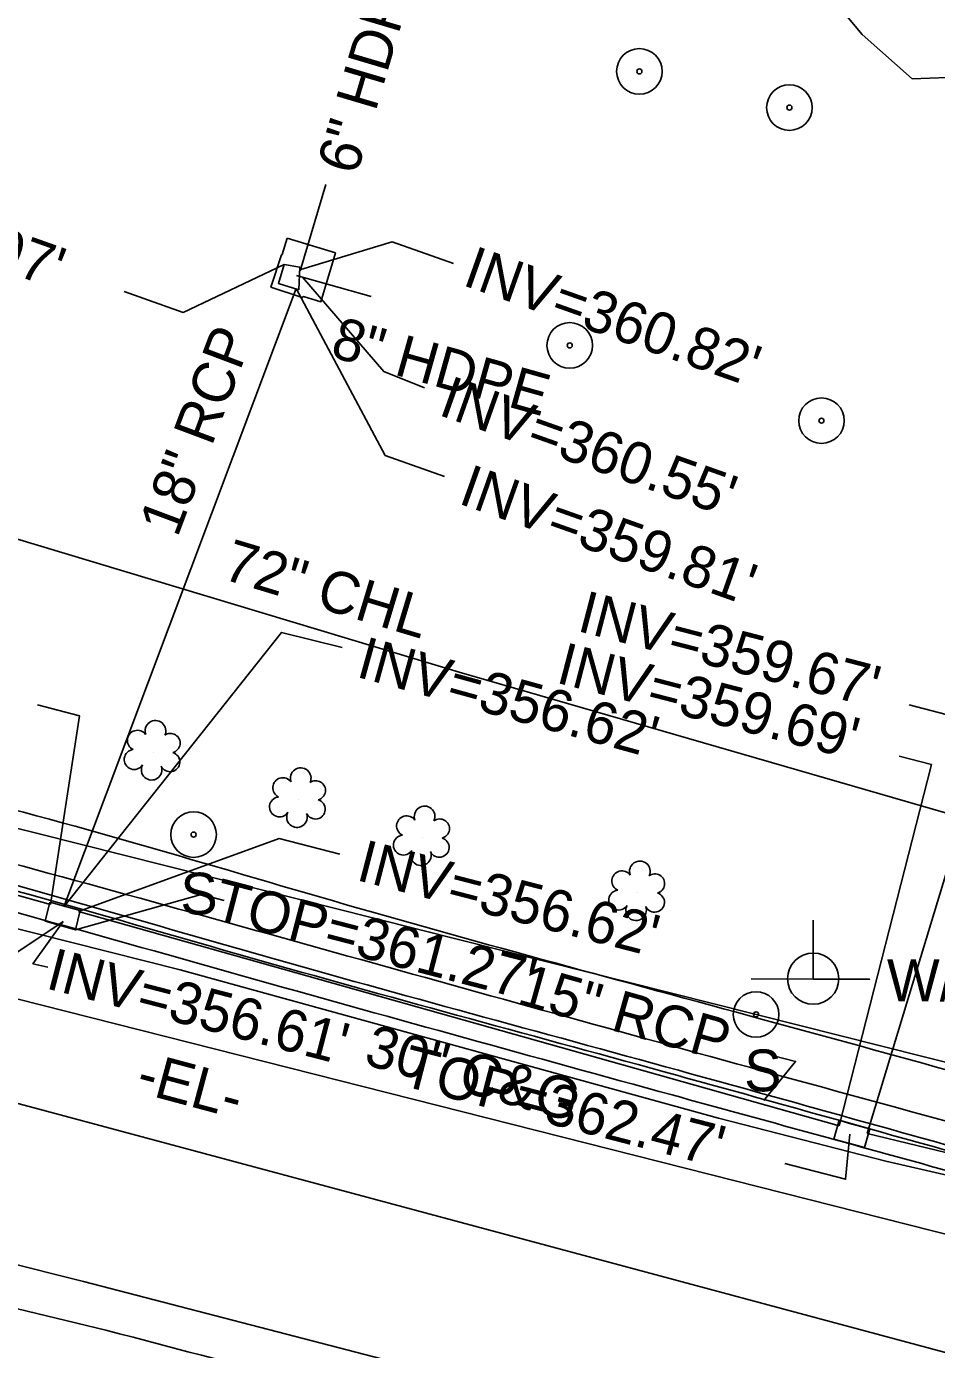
# Model space of a CAD drawing. Extents: x 2089016 to 2094354, y 862840 to 864725.
# Drawn here: x 2092382.6 to 2092469.8, y 863718.1 to 863844.8 of the extents above; entities that cross this region are included whole.
import ezdxf

# ---------------------------------------------------------------- set-up
doc = ezdxf.new("R2010")
doc.units = 0
for name, color, linetype in [('Exist Horizontal Alignment', 7, 'Continuous'), ('Exist Other Culture Area Outline', 7, 'Continuous'), ('Exist Other Culture Fence Line', 7, 'Continuous'), ('Exist Other Culture Fence Line Text', 7, 'Continuous'), ('Exist Other Culture Located Object CELL', 7, 'Continuous'), ('Exist Other Culture Sign Text', 7, 'Continuous'), ('Exist Right of Way Line', 7, 'Continuous'), ('Exist Roads Curbs', 7, 'Continuous'), ('Exist Roads Curbs Text', 7, 'Continuous'), ('Exist Roads EOP', 7, 'Continuous'), ('Exist Roads EOP Other', 7, 'Continuous'), ('Exist Structure Minor Drop Inlet', 7, 'Continuous'), ('Exist Structure Minor Drop Inlet Leader', 7, 'Continuous'), ('Exist Structure Minor Drop Inlet Top Elevation', 7, 'Continuous'), ('Exist Structure Minor Pipes HDPE 8 Inch', 7, 'Continuous'), ('Exist Structure Minor Pipes HDPE 8 Inch Invert', 7, 'Continuous'), ('Exist Structure Minor Pipes HDPE 8 Inch Leader', 7, 'Continuous'), ('Exist Structure Minor Pipes HDPE 8 Inch Text', 7, 'Continuous'), ('Exist Structure Minor Pipes RCP 15 Inch', 7, 'Continuous'), ('Exist Structure Minor Pipes RCP 15 Inch Invert', 7, 'Continuous'), ('Exist Structure Minor Pipes RCP 15 Inch Leader', 7, 'Continuous'), ('Exist Structure Minor Pipes RCP 15 Inch Text', 7, 'Continuous'), ('Exist Structure Minor Pipes RCP 18 Inch', 7, 'Continuous'), ('Exist Structure Minor Pipes RCP 18 Inch Invert', 7, 'Continuous'), ('Exist Structure Minor Pipes RCP 18 Inch Leader', 7, 'Continuous'), ('Exist Structure Minor Pipes RCP 18 Inch Text', 7, 'Continuous'), ('Exist Structure Minor Storm Sewer Line', 7, 'Continuous'), ('Exist Structure Minor Storm Sewer Line Leader', 7, 'Continuous'), ('Exist Structure Minor Storm Sewer Line Text', 7, 'Continuous'), ('Exist Utilities Gas UG Line SUE LOS B', 7, 'Continuous'), ('Exist Utilities Power Joint Use Telephone Text', 7, 'Continuous'), ('Exist Utilities Sanitary Sewer UG Line', 7, 'Continuous'), ('Exist Vegetation Shrub CELL', 7, 'Continuous'), ('Prop Conc Driveway', 7, 'Continuous'), ('Prop SS Fill Line', 7, 'Continuous'), ('R5707_NCDOT_FS_170814 - Exist Utilities Water UG Line SUE LOS B', 7, 'Continuous')]:
    doc.layers.add(name, color=color, linetype=linetype)

msp = doc.modelspace()

# ---------------------------------------------------------------- linework, layer by layer
at = {"layer": 'Exist Horizontal Alignment'}
msp.add_line((2092034.83, 863834.84), (2092760.56, 863639.99), dxfattribs=at)
at = {"layer": 'Exist Other Culture Area Outline'}
msp.add_lwpolyline([(2092448.89, 863913.79), (2092459.3, 863903.72), (2092470.45, 863890.73), (2092475.73, 863884.56), (2092478.99, 863877.48), (2092480.84, 863866.27), (2092480.53, 863859.37), (2092479.18, 863854.97), (2092481.61, 863848.81), (2092481.93, 863845.19), (2092480.71, 863841.34), (2092477.64, 863839.23), (2092470.83, 863839.92), (2092467.44, 863839.8), (2092462.66, 863844.05), (2092454.11, 863854.31), (2092447.77, 863862.3), (2092442.98, 863871.84), (2092439.73, 863883.85), (2092440.03, 863895.79), (2092441.59, 863906.81), (2092443.1, 863911.62), (2092445.28, 863913.82), (2092448.89, 863913.79)], dxfattribs=at)
at = {"layer": 'Exist Other Culture Fence Line'}
msp.add_lwpolyline([(2092413.53, 863932.41), (2092401.9, 863908.58), (2092388.06, 863866.85), (2092378.43, 863838.7), (2092365.14, 863800.74), (2092424.08, 863782.97), (2092472.06, 863769.09), (2092496.27, 863784.06), (2092487.92, 863824.43), (2092493.13, 863865.58), (2092487.72, 863879.2), (2092483.14, 863888.79), (2092478.4, 863896.79), (2092473.92, 863903.52), (2092467.94, 863910.24), (2092461.03, 863916), (2092452.82, 863921.39), (2092443, 863925.81), (2092433.04, 863928.49), (2092413.53, 863932.41)], dxfattribs=at)
at = {"layer": 'Exist Other Culture Located Object CELL'}
for centre, radius in [((2092441.32, 863840.51), 2.18), ((2092441.32, 863840.51), 0.24), ((2092455.68, 863837.04), 2.18), ((2092455.68, 863837.04), 0.24), ((2092434.65, 863814.27), 2.18), ((2092434.65, 863814.27), 0.24), ((2092458.75, 863807.06), 2.18), ((2092458.75, 863807.06), 0.24)]:
    msp.add_circle(centre, radius, dxfattribs=at)
at = {"layer": 'Exist Right of Way Line'}
msp.add_line((2092768.27, 863670.59), (2092317.44, 863784.24), dxfattribs=at)
at = {"layer": 'Exist Roads Curbs'}
for points in [[(2092353.2, 863866.71), (2092347.91, 863852.79), (2092342.21, 863837.8), (2092328.03, 863808.39), (2092326.02, 863803.79), (2092324.32, 863797.6), (2092324.25, 863794.81), (2092325.2, 863788.81), (2092327.18, 863784.11), (2092330.76, 863779.06), (2092334.2, 863776.06), (2092338.73, 863773.82), (2092365.53, 863766.27), (2092405.22, 863755.31), (2092444.92, 863744.37), (2092471.21, 863737.05), (2092516.32, 863724.63)], [(2092353.67, 863866.53), (2092348.38, 863852.62), (2092342.66, 863837.6), (2092328.49, 863808.18), (2092326.49, 863803.62), (2092324.82, 863797.52), (2092324.75, 863794.84), (2092325.68, 863788.94), (2092327.62, 863784.35), (2092331.14, 863779.4), (2092334.48, 863776.48), (2092338.91, 863774.28), (2092365.67, 863766.75), (2092405.35, 863755.8), (2092445.06, 863744.85), (2092471.34, 863737.53), (2092516.45, 863725.11)]]:
    msp.add_spline(points, degree=3, dxfattribs=at)
at = {"layer": 'Exist Roads EOP'}
msp.add_line((2092390.23, 863719.97), (2092367.28, 863725.48), dxfattribs=at)
for points in [[(2092351.39, 863867.42), (2092346.28, 863853.71), (2092340.44, 863838.83), (2092338.02, 863832.45), (2092326.59, 863809.54), (2092324.18, 863804.42), (2092322.34, 863798.11), (2092322.21, 863794.63), (2092323.26, 863788.18), (2092325.31, 863783.21), (2092329.49, 863777.7), (2092333.36, 863774.11), (2092338.14, 863771.94), (2092365.19, 863764.36), (2092404.76, 863753.49), (2092444.45, 863742.49), (2092470.82, 863735.23), (2092515.55, 863722.74), (2092529.36, 863718.89), (2092533.92, 863717.65), (2092575.11, 863706.35), (2092620.49, 863693.63), (2092661.52, 863682.27), (2092704.83, 863670.36)], [(2092733.96, 863624.56), (2092729.42, 863627.24), (2092710.26, 863638.22), (2092685.56, 863646.14), (2092644.34, 863656.7), (2092636.3, 863658.85), (2092633.44, 863659.08), (2092631.45, 863657.89), (2092628.59, 863656.45), (2092626.77, 863655.79), (2092624.31, 863656.27), (2092613.98, 863659.23), (2092588.53, 863665.82), (2092584.48, 863666.74), (2092582.65, 863668.4), (2092580.87, 863671.65), (2092573.74, 863674.74), (2092530.78, 863685.35), (2092492.66, 863694.32), (2092471.57, 863699.61), (2092432.29, 863709.14), (2092390.23, 863719.97)]]:
    msp.add_spline(points, degree=3, dxfattribs=at)
at = {"layer": 'Exist Roads EOP Other'}
msp.add_lwpolyline([(2092407.59, 863824.53), (2092407.11, 863822.98), (2092407.07, 863822.93), (2092406.04, 863819.85), (2092409.05, 863818.86), (2092409.18, 863818.95), (2092410.84, 863818.45), (2092412.23, 863823.12), (2092407.59, 863824.53)], dxfattribs=at)
for points in [[(2092744.83, 863669.14), (2092739.53, 863670.51), (2092698.61, 863681.9), (2092655.56, 863693.83), (2092614.88, 863705.04), (2092572.51, 863716.82), (2092534.25, 863727.26), (2092490.85, 863739.3), (2092453.11, 863749.73), (2092413.17, 863760.74), (2092373.71, 863771.76), (2092342.37, 863780.54), (2092336.27, 863784.25), (2092333.6, 863789.3), (2092333.19, 863795.1), (2092333.89, 863798.65), (2092336.05, 863803.25), (2092354.66, 863838.72)], [(2092743.53, 863664.36), (2092738.18, 863665.86), (2092697.44, 863677.09), (2092654.51, 863689.14), (2092613.57, 863700.33), (2092571.3, 863712.05), (2092533.04, 863722.78), (2092489.78, 863734.76), (2092451.86, 863745.14), (2092412.17, 863756.14), (2092372.39, 863767.04), (2092340.78, 863775.86), (2092336.36, 863777.72), (2092332.77, 863780.97)]]:
    msp.add_spline(points, degree=3, dxfattribs=at)
at = {"layer": 'Exist Structure Minor Drop Inlet'}
for points in [[(2092408.71, 863819.58), (2092408.82, 863821.75), (2092407.31, 863822.02), (2092406.76, 863820.2), (2092408.71, 863819.58)], [(2092384.88, 863760.95), (2092384.44, 863759.12), (2092387.33, 863758.3), (2092387.8, 863760.15), (2092384.88, 863760.95)], [(2092460.43, 863740.09), (2092459.95, 863738.27), (2092462.87, 863737.45), (2092463.37, 863739.26), (2092460.43, 863740.09)]]:
    msp.add_lwpolyline(points, dxfattribs=at)
at = {"layer": 'Exist Structure Minor Drop Inlet Leader'}
for points in [[(2092407.31, 863822.02), (2092397.64, 863817.42), (2092391.99, 863819.43)], [(2092387.33, 863758.3), (2092399.37, 863761.67), (2092401.58, 863761.11)], [(2092461.48, 863738.73), (2092461.06, 863734.42), (2092455.25, 863735.93)]]:
    msp.add_lwpolyline(points, dxfattribs=at)
at = {"layer": 'Exist Structure Minor Pipes HDPE 8 Inch'}
msp.add_line((2092408.5, 863820.96), (2092415.63, 863818.96), dxfattribs=at)
at = {"layer": 'Exist Structure Minor Pipes HDPE 8 Inch Leader'}
msp.add_lwpolyline([(2092409.06, 863820.8), (2092416.85, 863811.76), (2092420.75, 863810.2)], dxfattribs=at)
at = {"layer": 'Exist Structure Minor Pipes RCP 15 Inch'}
for p, q in [((2092341.48, 863772.81), (2092384.96, 863760.73)), ((2092387.63, 863760.07), (2092460.44, 863739.53)), ((2092463.12, 863738.81), (2092521.59, 863724.59))]:
    msp.add_line(p, q, dxfattribs=at)
at = {"layer": 'Exist Structure Minor Pipes RCP 15 Inch Leader'}
for points in [[(2092384.96, 863760.73), (2092387.71, 863778.81), (2092383.71, 863779.84)], [(2092463.12, 863738.81), (2092474.96, 863777.82), (2092467.16, 863779.84)], [(2092460.44, 863739.53), (2092469.28, 863774.12), (2092466.2, 863774.92)], [(2092387.63, 863760.07), (2092406.85, 863767.04), (2092412.66, 863765.54)], [(2092453.23, 863741.95), (2092456.27, 863745.7), (2092454.17, 863746.25)]]:
    msp.add_lwpolyline(points, dxfattribs=at)
at = {"layer": 'Exist Structure Minor Pipes RCP 18 Inch'}
for p, q in [((2092386.21, 863760.49), (2092408.45, 863819.71)), ((2092386.16, 863759.09), (2092332.67, 863723.61))]:
    msp.add_line(p, q, dxfattribs=at)
at = {"layer": 'Exist Structure Minor Pipes RCP 18 Inch Leader'}
for points in [[(2092408.45, 863819.71), (2092416.99, 863803.73), (2092422.65, 863801.72)], [(2092386.21, 863760.49), (2092407.06, 863786.79), (2092412.88, 863785.35)], [(2092386.16, 863759.09), (2092383.26, 863755.06), (2092384.69, 863754.74)]]:
    msp.add_lwpolyline(points, dxfattribs=at)
at = {"layer": 'Exist Structure Minor Storm Sewer Line'}
msp.add_line((2092408.84, 863821.4), (2092411.3, 863829.68), dxfattribs=at)
at = {"layer": 'Exist Structure Minor Storm Sewer Line Leader'}
msp.add_lwpolyline([(2092408.91, 863821.53), (2092417.66, 863824.19), (2092423.54, 863822.1)], dxfattribs=at)
at = {"layer": 'Exist Utilities Gas UG Line SUE LOS B'}
msp.add_lwpolyline([(2092155.53, 863822.55), (2092186.43, 863814.74), (2092212.98, 863806.03), (2092237.86, 863798.34), (2092260.45, 863791.36), (2092300.12, 863779.39), (2092314.5, 863775.84), (2092322.83, 863773.36), (2092328.49, 863771.73), (2092349.13, 863766.64), (2092397.35, 863754.46), (2092448.88, 863740.26), (2092464.92, 863736.14), (2092490.33, 863730.32), (2092507.98, 863725.93), (2092525.93, 863721.3), (2092530.05, 863719.77)], dxfattribs=at)
at = {"layer": 'Exist Utilities Sanitary Sewer UG Line'}
msp.add_lwpolyline([(2091909.39, 863878.94), (2092144.37, 863811.51), (2092367.47, 863755.3), (2092545.21, 863710.25)], dxfattribs=at)
at = {"layer": 'Exist Vegetation Shrub CELL'}
for p, q in [((2092394.76, 863775.31), (2092394.76, 863775.31)), ((2092408.67, 863770.78), (2092408.67, 863770.78)), ((2092420.53, 863767.12), (2092420.53, 863767.12)), ((2092441.14, 863761.86), (2092441.14, 863761.86))]:
    msp.add_line(p, q, dxfattribs=at)
for centre, radius, start, end in [((2092394.99, 863777.35), 0.99, 334.8391, 200.4717), ((2092393.27, 863776.44), 0.968, 35.8908, 245.4216), ((2092396.43, 863776.18), 0.929, 284.4567, 126.0861), ((2092392.96, 863774.61), 0.955, 95.1099, 327.9534), ((2092396.39, 863774.38), 0.937, 204.9913, 73.4601), ((2092394.63, 863773.63), 0.984, 151.2797, 21.387), ((2092408.9, 863772.82), 0.99, 334.8391, 200.4717), ((2092407.19, 863771.9), 0.968, 35.8908, 245.4216), ((2092410.34, 863771.65), 0.929, 284.4567, 126.0861), ((2092406.87, 863770.07), 0.955, 95.1099, 327.9534), ((2092410.31, 863769.85), 0.937, 204.9913, 73.4601), ((2092408.54, 863769.09), 0.984, 151.2797, 21.387), ((2092419.05, 863768.25), 0.968, 35.8908, 245.4216), ((2092420.76, 863769.16), 0.99, 334.8391, 200.4717), ((2092422.21, 863767.99), 0.929, 284.4567, 126.0861), ((2092418.73, 863766.42), 0.955, 95.1099, 327.9534), ((2092422.17, 863766.19), 0.937, 204.9913, 73.4601), ((2092420.41, 863765.44), 0.984, 151.2797, 21.387), ((2092441.37, 863763.9), 0.99, 334.8391, 200.4717), ((2092439.66, 863762.98), 0.968, 35.8908, 245.4216), ((2092442.81, 863762.73), 0.929, 284.4567, 126.0861), ((2092439.34, 863761.15), 0.955, 95.1099, 327.9534), ((2092442.78, 863760.93), 0.937, 204.9913, 73.4601), ((2092441.01, 863760.17), 0.984, 151.2797, 21.387)]:
    msp.add_arc(centre, radius, start, end, dxfattribs=at)
at = {"layer": 'Prop Conc Driveway'}
for centre, radius in [((2092398.65, 863767.42), 2.18), ((2092398.65, 863767.42), 0.24), ((2092452.49, 863750.2), 2.18), ((2092452.49, 863750.2), 0.24)]:
    msp.add_circle(centre, radius, dxfattribs=at)
at = {"layer": 'Prop SS Fill Line'}
msp.add_line((2092457.96, 863753.61), (2092457.96, 863753.61), dxfattribs=at)
msp.add_lwpolyline([(2092452.02, 863753.61), (2092463.36, 863753.57), (2092457.96, 863753.59), (2092457.96, 863759.24)], dxfattribs=at)
msp.add_circle((2092457.96, 863753.62), 2.45, dxfattribs=at)
at = {"layer": 'R5707_NCDOT_FS_170814 - Exist Utilities Water UG Line SUE LOS B'}
msp.add_lwpolyline([(2092148.05, 863786.14), (2092203, 863772.13), (2092252.38, 863759.3), (2092290.53, 863749.54), (2092340.79, 863736.5), (2092388.1, 863724.64), (2092438.64, 863711.49), (2092487.77, 863698.79), (2092489.84, 863698), (2092492.87, 863697.04), (2092516.39, 863691.48), (2092553.58, 863682.15), (2092619.75, 863665.41), (2092671.68, 863651.84)], dxfattribs=at)

# ---------------------------------------------------------------- texts
at = {"layer": 'Exist Horizontal Alignment'}
msp.add_text('-EL-', height=4, rotation=344.9717, dxfattribs=at).set_placement((2092392.98, 863742.82))
at = {"layer": 'Exist Other Culture Fence Line Text'}
msp.add_text('72" CHL', height=4, rotation=343.2302, dxfattribs=at).set_placement((2092401.27, 863791.94))
at = {"layer": 'Exist Other Culture Sign Text'}
for p in [(2092397.38, 863759.77), (2092451.35, 863742.84)]:
    msp.add_text('S', height=4, dxfattribs=at).set_placement(p)
at = {"layer": 'Exist Roads Curbs Text'}
msp.add_text('30" C&G', height=4, rotation=344.4837, dxfattribs=at).set_placement((2092414.81, 863745.45))
at = {"layer": 'Exist Structure Minor Drop Inlet Top Elevation'}
for s, rotation, p in [("TOP=366.97'", 340.4691, (2092355.71, 863830.17)), ("TOP=361.27'", 345.4489, (2092400.3, 863759.38)), ("TOP=362.47'", 345.4489, (2092418.36, 863743.44))]:
    msp.add_text(s, height=4, rotation=rotation, dxfattribs=at).set_placement(p)
at = {"layer": 'Exist Structure Minor Pipes HDPE 8 Inch Invert'}
for s, p in [("INV=360.82'", (2092424.26, 863820.08)), ("INV=360.55'", (2092421.96, 863807.65))]:
    msp.add_text(s, height=4, rotation=340.4691, dxfattribs=at).set_placement(p)
at = {"layer": 'Exist Structure Minor Pipes HDPE 8 Inch Text'}
msp.add_text('8" HDPE', height=4, rotation=344.2969, dxfattribs=at).set_placement((2092411.6, 863813.22))
at = {"layer": 'Exist Structure Minor Pipes RCP 15 Inch Invert'}
for s, p in [("INV=359.67'", (2092435.24, 863786.95)), ("INV=359.69'", (2092433.22, 863782)), ("INV=356.62'", (2092414.09, 863763.1))]:
    msp.add_text(s, height=4, rotation=345.4489, dxfattribs=at).set_placement(p)
at = {"layer": 'Exist Structure Minor Pipes RCP 15 Inch Text'}
msp.add_text('15" RCP', height=4, rotation=344.2467, dxfattribs=at).set_placement((2092429.48, 863751.26))
at = {"layer": 'Exist Structure Minor Pipes RCP 18 Inch Invert'}
for s, rotation, p in [("INV=359.81'", 340.4691, (2092423.86, 863799.17)), ("INV=356.62'", 344.55, (2092414.09, 863782.57)), ("INV=356.61'", 345.4489, (2092384.37, 863752.73))]:
    msp.add_text(s, height=4, rotation=rotation, dxfattribs=at).set_placement(p)
at = {"layer": 'Exist Structure Minor Pipes RCP 18 Inch Text'}
msp.add_text('18" RCP', height=4, rotation=69.4157, dxfattribs=at).set_placement((2092397.09, 863795.79))
at = {"layer": 'Exist Structure Minor Storm Sewer Line Text'}
msp.add_text('6" HDPE', height=4, rotation=73.4784, dxfattribs=at).set_placement((2092414.24, 863830.47))
at = {"layer": 'Exist Utilities Power Joint Use Telephone Text'}
msp.add_text('W/LT', height=4, dxfattribs=at).set_placement((2092465.02, 863751.47))

doc.saveas('drawing.dxf')
